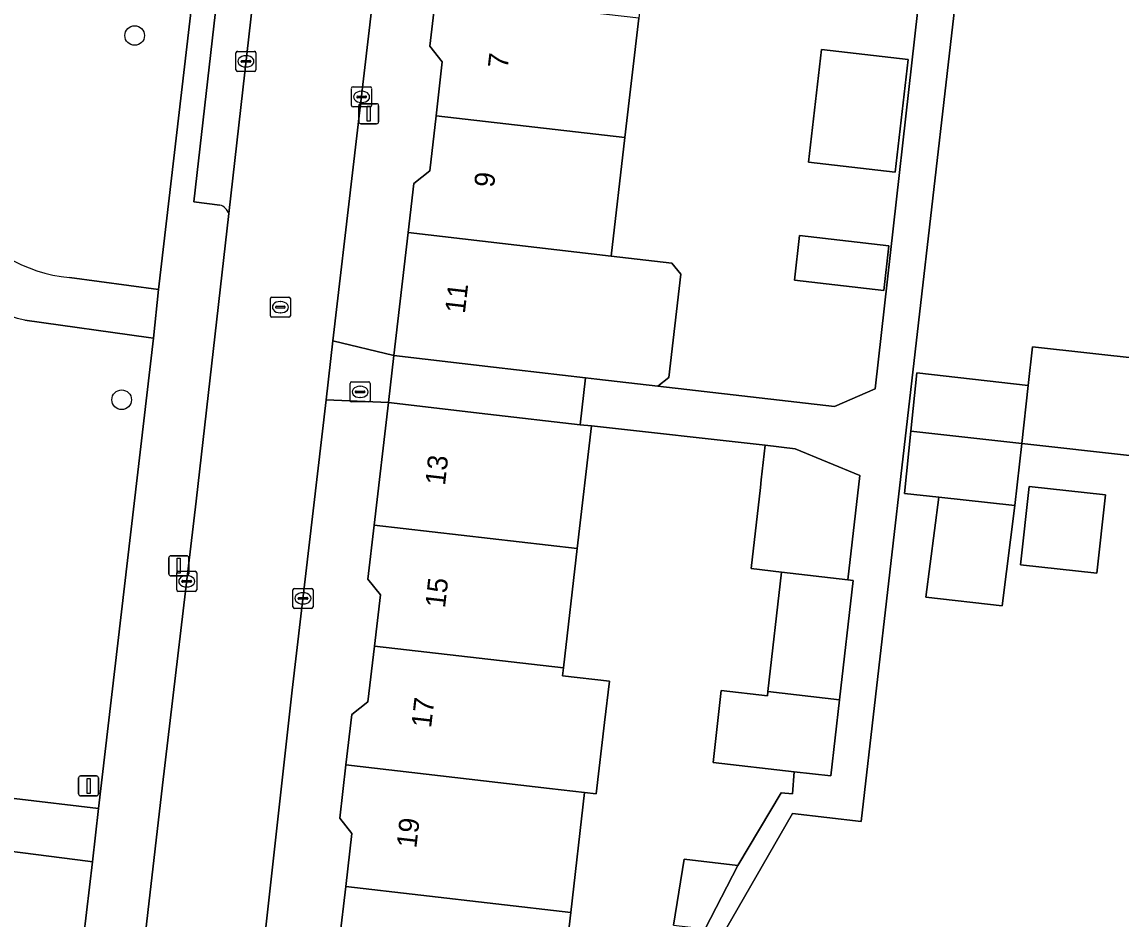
# Model space of a CAD drawing. Extents: x 161692 to 162379, y 380760 to 381678.
# Drawn here: x 162152.4 to 162207.2, y 381154.7 to 381199.4 of the extents above; entities that cross this region are included whole.
import ezdxf

# ---------------------------------------------------------------- set-up
doc = ezdxf.new("R2010")
doc.units = 0
for name, color, linetype in [('IMGEO_Boom', 7, 'Continuous'), ('IMGEO_Brandkraan', 7, 'Continuous'), ('IMGEO_Erf', 7, 'Continuous'), ('IMGEO_Groenvoorziening', 7, 'Continuous'), ('IMGEO_Kolk', 7, 'Continuous'), ('IMGEO_Lichtmast', 7, 'Continuous'), ('IMGEO_Pand', 7, 'Continuous'), ('IMGEO_Pand_nummerreeks', 7, 'Continuous'), ('IMGEO_Pand_overbouw', 7, 'Continuous'), ('IMGEO_Parkeervlak_open', 7, 'Continuous'), ('IMGEO_Rijbaan_lokaal_open', 7, 'Continuous'), ('IMGEO_Rioolput', 7, 'Continuous'), ('IMGEO_Verkeersbordpaal', 7, 'Continuous'), ('IMGEO_Voetpad_gesloten', 7, 'Continuous'), ('IMGEO_Voetpad_open', 7, 'Continuous')]:
    doc.layers.add(name, color=color, linetype=linetype)

msp = doc.modelspace()

# ---------------------------------------------------------------- linework, layer by layer
at = {"layer": 'IMGEO_Boom'}
for centre in [(162157.976, 381198.758), (162157.326, 381180.592)]:
    msp.add_circle(centre, 0.489, dxfattribs=at)
at = {"layer": 'IMGEO_Brandkraan'}
for p, q in [((162168.72, 381180.558), (162168.72, 381181.41)), ((162168.795, 381181.484), (162169.647, 381181.484)), ((162169.208, 381181.264), (162169.233, 381181.264)), ((162169.721, 381181.41), (162169.721, 381180.558)), ((162168.979, 381180.978), (162168.979, 381180.99)), ((162169.417, 381180.941), (162169.019, 381180.941)), ((162169.022, 381181.027), (162169.42, 381181.027)), ((162169.231, 381180.704), (162169.206, 381180.704)), ((162169.463, 381180.99), (162169.463, 381180.978)), ((162169.647, 381180.484), (162168.795, 381180.484))]:
    msp.add_line(p, q, dxfattribs=at)
for points in [[(162168.72, 381180.558), (162168.72, 381181.41)], [(162168.795, 381181.484), (162169.647, 381181.484)], [(162169.721, 381181.41), (162169.721, 381180.558)], [(162169.647, 381180.484), (162168.795, 381180.484)]]:
    msp.add_lwpolyline(points, dxfattribs=at)
for centre, radius, start, end in [((162168.797, 381181.408), 0.0765, 91.552, 178.448), ((162168.797, 381181.408), 0.0765, 91.552, 178.448), ((162169.645, 381181.408), 0.0765, 1.552, 88.448), ((162169.645, 381181.408), 0.0765, 1.552, 88.448), ((162169.019, 381180.987), 0.0403, 85.8775, 175.7526), ((162169.016, 381180.977), 0.0366, 178.938, 274.7102), ((162169.42, 381180.984), 0.043, 264.8664, 352.4533), ((162169.424, 381180.989), 0.0386, 1.7309, 96.639), ((162168.797, 381180.56), 0.0765, 181.552, 268.448), ((162168.797, 381180.56), 0.0765, 181.552, 268.448), ((162169.645, 381180.56), 0.0765, 271.552, 358.448), ((162169.645, 381180.56), 0.0765, 271.552, 358.448)]:
    msp.add_arc(centre, radius, start, end, dxfattribs=at)
for centre, major_axis, ratio, start_param, end_param in [((162169.207, 381180.984), (-0.387, 0.002), 0.722429, 4.712389, 7.853982), ((162169.232, 381180.984), (-0.39, 0.002), 0.717154, 1.570796, 4.712389)]:
    msp.add_ellipse(centre, major_axis=major_axis, ratio=ratio, start_param=start_param, end_param=end_param, dxfattribs=at)
at = {"layer": 'IMGEO_Erf'}
for points in [[(162197.492, 381204.07), (162195.227, 381204.349), (162195.955, 381210.26), (162195.971, 381210.391), (162184.525, 381211.801), (162184.5, 381211.582), (162183.822, 381205.729), (162183.114, 381199.619), (162182.424, 381193.665), (162181.74, 381187.759), (162184.774, 381187.407), (162185.214, 381186.853), (162184.617, 381181.706), (162184.063, 381181.267), (162192.874, 381180.248), (162194.906, 381181.141)], [(162191.586, 381192.438), (162192.238, 381198.066), (162196.558, 381197.565), (162195.906, 381191.937)], [(162190.88, 381186.561), (162191.136, 381188.782), (162195.597, 381188.268), (162195.341, 381186.047)], [(162205.964, 381171.947), (162202.16, 381172.366), (162202.589, 381176.267), (162206.394, 381175.848)]]:
    msp.add_lwpolyline(points, close=True, dxfattribs=at)
for points in [[(162207.712, 381201.997), (162204.798, 381202.356), (162201.896, 381202.774), (162199.213, 381203.105), (162194.213, 381159.563), (162190.787, 381159.956), (162187.187, 381153.72)], [(162207.751, 381177.797), (162202.224, 381178.406), (162201.877, 381175.315), (162201.236, 381170.321), (162197.439, 381170.74), (162198.08, 381175.734), (162196.379, 381175.921), (162196.694, 381179.03), (162196.989, 381181.931), (162202.544, 381181.305), (162202.756, 381183.23), (162208.321, 381182.616)], [(162184.851, 381154.388), (162185.377, 381157.678), (162188.067, 381157.367), (162190.225, 381160.981), (162190.784, 381160.938), (162190.869, 381162.044), (162186.824, 381162.507), (162187.235, 381166.095), (162189.531, 381165.832), (162189.555, 381166.041), (162190.238, 381171.997), (162188.723, 381172.171), (162189.186, 381176.211), (162189.221, 381176.596), (162189.419, 381178.324), (162180.759, 381179.284), (162180.051, 381173.174), (162179.361, 381167.219), (162179.316, 381166.83), (162181.652, 381166.559), (162181.413, 381164.501), (162181.001, 381160.942), (162180.418, 381161.01), (162179.724, 381155.017), (162179.03, 381149.027)]]:
    msp.add_lwpolyline(points, dxfattribs=at)
at = {"layer": 'IMGEO_Groenvoorziening'}
for points in [[(162154.726, 381186.684), (162159.161, 381186.093), (162161.466, 381205.753)], [(162158.923, 381183.669), (162158.67, 381183.704), (162152.495, 381184.57)], [(162135.13, 381162.697), (162156.168, 381160.201), (162158.923, 381183.669)], [(162106.694, 381166.723), (162106.422, 381166.149), (162104.701, 381153.539), (162105.038, 381151.871), (162154.533, 381146.175), (162155.871, 381157.555), (162155.636, 381157.584), (162133.829, 381160.381)]]:
    msp.add_lwpolyline(points, dxfattribs=at)
for centre, radius, start, end in [((162155.544, 381194.539), 7.898, 215.9918, 264.0544), ((162154.454, 381193.294), 8.941, 217.9373, 257.3448)]:
    msp.add_arc(centre, radius, start, end, dxfattribs=at)
at = {"layer": 'IMGEO_Kolk'}
for p, q in [((162163.025, 381197.043), (162163.025, 381197.895)), ((162163.1, 381197.969), (162163.952, 381197.969)), ((162163.513, 381197.749), (162163.538, 381197.749)), ((162164.026, 381197.895), (162164.026, 381197.043)), ((162163.284, 381197.463), (162163.284, 381197.475)), ((162163.722, 381197.426), (162163.324, 381197.426)), ((162163.327, 381197.512), (162163.725, 381197.512)), ((162163.536, 381197.189), (162163.511, 381197.189)), ((162163.768, 381197.475), (162163.768, 381197.463)), ((162163.952, 381196.969), (162163.1, 381196.969)), ((162168.792, 381195.272), (162168.792, 381196.124)), ((162168.867, 381196.198), (162169.719, 381196.198)), ((162169.28, 381195.978), (162169.305, 381195.978)), ((162169.793, 381196.124), (162169.793, 381195.272)), ((162169.051, 381195.692), (162169.051, 381195.704)), ((162169.489, 381195.655), (162169.091, 381195.655)), ((162169.094, 381195.741), (162169.492, 381195.741)), ((162169.303, 381195.418), (162169.278, 381195.418)), ((162169.535, 381195.704), (162169.535, 381195.692)), ((162169.719, 381195.198), (162168.867, 381195.198)), ((162160.071, 381171.111), (162160.071, 381171.963)), ((162160.146, 381172.037), (162160.998, 381172.037)), ((162161.072, 381171.963), (162161.072, 381171.111)), ((162160.33, 381171.531), (162160.33, 381171.543)), ((162160.768, 381171.494), (162160.37, 381171.494)), ((162160.373, 381171.58), (162160.771, 381171.58)), ((162160.559, 381171.817), (162160.584, 381171.817)), ((162160.814, 381171.543), (162160.814, 381171.531)), ((162160.998, 381171.037), (162160.146, 381171.037)), ((162160.582, 381171.257), (162160.557, 381171.257)), ((162165.869, 381170.261), (162165.869, 381171.113)), ((162165.944, 381171.187), (162166.796, 381171.187)), ((162166.171, 381170.73), (162166.569, 381170.73)), ((162166.357, 381170.967), (162166.382, 381170.967)), ((162166.87, 381171.113), (162166.87, 381170.261)), ((162166.796, 381170.187), (162165.944, 381170.187)), ((162166.128, 381170.681), (162166.128, 381170.693)), ((162166.566, 381170.644), (162166.168, 381170.644)), ((162166.38, 381170.407), (162166.355, 381170.407)), ((162166.612, 381170.693), (162166.612, 381170.681))]:
    msp.add_line(p, q, dxfattribs=at)
for points in [[(162163.025, 381197.043), (162163.025, 381197.895)], [(162163.1, 381197.969), (162163.952, 381197.969)], [(162164.026, 381197.895), (162164.026, 381197.043)], [(162163.952, 381196.969), (162163.1, 381196.969)], [(162168.792, 381195.272), (162168.792, 381196.124)], [(162168.867, 381196.198), (162169.719, 381196.198)], [(162169.793, 381196.124), (162169.793, 381195.272)], [(162169.719, 381195.198), (162168.867, 381195.198)], [(162160.071, 381171.111), (162160.071, 381171.963)], [(162160.146, 381172.037), (162160.998, 381172.037)], [(162161.072, 381171.963), (162161.072, 381171.111)], [(162160.998, 381171.037), (162160.146, 381171.037)], [(162165.869, 381170.261), (162165.869, 381171.113)], [(162165.944, 381171.187), (162166.796, 381171.187)], [(162166.87, 381171.113), (162166.87, 381170.261)], [(162166.796, 381170.187), (162165.944, 381170.187)]]:
    msp.add_lwpolyline(points, dxfattribs=at)
for centre, radius, start, end in [((162163.102, 381197.893), 0.0765, 91.552, 178.448), ((162163.102, 381197.893), 0.0765, 91.552, 178.448), ((162163.95, 381197.893), 0.0765, 1.552, 88.448), ((162163.95, 381197.893), 0.0765, 1.552, 88.448), ((162163.102, 381197.045), 0.0765, 181.552, 268.448), ((162163.102, 381197.045), 0.0765, 181.552, 268.448), ((162163.324, 381197.472), 0.0403, 85.8775, 175.7526), ((162163.321, 381197.462), 0.0366, 178.938, 274.7102), ((162163.725, 381197.469), 0.043, 264.8664, 352.4533), ((162163.729, 381197.474), 0.0386, 1.7309, 96.639), ((162163.95, 381197.045), 0.0765, 271.552, 358.448), ((162163.95, 381197.045), 0.0765, 271.552, 358.448), ((162168.869, 381196.122), 0.0765, 91.552, 178.448), ((162168.869, 381196.122), 0.0765, 91.552, 178.448), ((162169.717, 381196.122), 0.0765, 1.552, 88.448), ((162169.717, 381196.122), 0.0765, 1.552, 88.448), ((162169.091, 381195.701), 0.0403, 85.8775, 175.7526), ((162169.088, 381195.691), 0.0366, 178.938, 274.7102), ((162169.492, 381195.698), 0.043, 264.8664, 352.4533), ((162169.496, 381195.703), 0.0386, 1.7309, 96.639), ((162168.869, 381195.274), 0.0765, 181.552, 268.448), ((162168.869, 381195.274), 0.0765, 181.552, 268.448), ((162169.717, 381195.274), 0.0765, 271.552, 358.448), ((162169.717, 381195.274), 0.0765, 271.552, 358.448), ((162160.148, 381171.961), 0.0765, 91.552, 178.448), ((162160.148, 381171.961), 0.0765, 91.552, 178.448), ((162160.996, 381171.961), 0.0765, 1.552, 88.448), ((162160.996, 381171.961), 0.0765, 1.552, 88.448), ((162160.37, 381171.54), 0.0403, 85.8775, 175.7526), ((162160.367, 381171.53), 0.0366, 178.938, 274.7102), ((162160.771, 381171.537), 0.043, 264.8664, 352.4533), ((162160.775, 381171.542), 0.0386, 1.7309, 96.639), ((162160.148, 381171.113), 0.0765, 181.552, 268.448), ((162160.148, 381171.113), 0.0765, 181.552, 268.448), ((162160.996, 381171.113), 0.0765, 271.552, 358.448), ((162160.996, 381171.113), 0.0765, 271.552, 358.448), ((162165.946, 381171.111), 0.0765, 91.552, 178.448), ((162165.946, 381171.111), 0.0765, 91.552, 178.448), ((162166.168, 381170.69), 0.0403, 85.8775, 175.7526), ((162166.573, 381170.692), 0.0386, 1.7309, 96.639), ((162166.794, 381171.111), 0.0765, 1.552, 88.448), ((162166.794, 381171.111), 0.0765, 1.552, 88.448), ((162165.946, 381170.263), 0.0765, 181.552, 268.448), ((162165.946, 381170.263), 0.0765, 181.552, 268.448), ((162166.165, 381170.68), 0.0366, 178.938, 274.7102), ((162166.569, 381170.687), 0.043, 264.8664, 352.4533), ((162166.794, 381170.263), 0.0765, 271.552, 358.448), ((162166.794, 381170.263), 0.0765, 271.552, 358.448)]:
    msp.add_arc(centre, radius, start, end, dxfattribs=at)
for centre, major_axis, ratio, start_param, end_param in [((162163.512, 381197.469), (-0.387, 0.002), 0.722429, 4.712389, 7.853982), ((162163.537, 381197.469), (-0.39, 0.002), 0.717154, 1.570796, 4.712389), ((162169.279, 381195.698), (-0.387, 0.002), 0.722429, 4.712389, 7.853982), ((162169.304, 381195.698), (-0.39, 0.002), 0.717154, 1.570796, 4.712389), ((162160.558, 381171.537), (-0.387, 0.002), 0.722429, 4.712389, 7.853982), ((162160.583, 381171.537), (-0.39, 0.002), 0.717154, 1.570796, 4.712389), ((162166.356, 381170.687), (-0.387, 0.002), 0.722429, 4.712389, 7.853982), ((162166.381, 381170.687), (-0.39, 0.002), 0.717154, 1.570796, 4.712389)]:
    msp.add_ellipse(centre, major_axis=major_axis, ratio=ratio, start_param=start_param, end_param=end_param, dxfattribs=at)
at = {"layer": 'IMGEO_Lichtmast'}
for p, q in [((162169.155, 381194.456), (162169.155, 381195.256)), ((162169.155, 381195.256), (162169.155, 381194.456)), ((162169.255, 381195.356), (162170.045, 381195.356)), ((162170.045, 381195.356), (162169.255, 381195.356)), ((162170.145, 381195.256), (162170.145, 381194.456)), ((162170.145, 381194.456), (162170.145, 381195.256)), ((162170.045, 381194.356), (162169.255, 381194.356)), ((162169.255, 381194.356), (162170.045, 381194.356)), ((162159.679, 381171.911), (162159.679, 381172.711)), ((162159.679, 381172.711), (162159.679, 381171.911)), ((162159.779, 381172.811), (162160.569, 381172.811)), ((162160.569, 381172.811), (162159.779, 381172.811)), ((162160.669, 381172.711), (162160.669, 381171.911)), ((162160.669, 381171.911), (162160.669, 381172.711)), ((162160.569, 381171.811), (162159.779, 381171.811)), ((162159.779, 381171.811), (162160.569, 381171.811))]:
    msp.add_line(p, q, dxfattribs=at)
for points in [[(162169.575, 381195.231), (162169.725, 381195.231), (162169.725, 381194.481), (162169.575, 381194.481), (162169.575, 381195.231)], [(162160.099, 381172.686), (162160.249, 381172.686), (162160.249, 381171.936), (162160.099, 381171.936), (162160.099, 381172.686)]]:
    msp.add_lwpolyline(points, dxfattribs=at)
for centre, start, end in [((162169.255, 381195.256), 90, 180), ((162169.255, 381195.256), 90, 180), ((162170.045, 381195.256), 0, 90), ((162170.045, 381195.256), 360, 90), ((162169.255, 381194.456), 180, 270), ((162169.255, 381194.456), 180, 270), ((162170.045, 381194.456), 270, 0), ((162170.045, 381194.456), 270, 0), ((162159.779, 381172.711), 90, 180), ((162159.779, 381172.711), 90, 180), ((162160.569, 381172.711), 0, 90), ((162160.569, 381172.711), 360, 90), ((162159.779, 381171.911), 180, 270), ((162159.779, 381171.911), 180, 270), ((162160.569, 381171.911), 270, 0), ((162160.569, 381171.911), 270, 0)]:
    msp.add_arc(centre, 0.1, start, end, dxfattribs=at)
at = {"layer": 'IMGEO_Pand'}
for points in [[(162173, 381200.786), (162172.703, 381198.226), (162173.32, 381197.448), (162173.008, 381194.753), (162182.424, 381193.665), (162183.114, 381199.619)], [(162191.586, 381192.438), (162195.906, 381191.937), (162196.558, 381197.565), (162192.238, 381198.066)], [(162171.61, 381188.928), (162181.74, 381187.759), (162182.424, 381193.665), (162173.008, 381194.753), (162172.69, 381192.008), (162171.894, 381191.377)], [(162171.61, 381188.928), (162170.9, 381182.792), (162175.867, 381182.216), (162180.461, 381181.684), (162181.029, 381181.618), (162184.063, 381181.267), (162184.617, 381181.706), (162185.214, 381186.853), (162184.774, 381187.407), (162181.74, 381187.759)], [(162190.88, 381186.561), (162195.341, 381186.047), (162195.597, 381188.268), (162191.136, 381188.782)], [(162208.321, 381182.616), (162202.756, 381183.23), (162202.544, 381181.305), (162202.224, 381178.406), (162207.751, 381177.797), (162207.852, 381178.768), (162207.866, 381178.766), (162207.957, 381179.536)], [(162202.544, 381181.305), (162196.989, 381181.931), (162196.694, 381179.03), (162202.224, 381178.406)], [(162169.921, 381174.343), (162180.051, 381173.174), (162180.759, 381179.284), (162180.19, 381179.35), (162175.597, 381179.882), (162170.63, 381180.457)], [(162202.224, 381178.406), (162196.694, 381179.03), (162196.379, 381175.921), (162198.08, 381175.734), (162201.877, 381175.315)], [(162189.419, 381178.324), (162189.221, 381176.596), (162189.186, 381176.211), (162188.723, 381172.171), (162190.238, 381171.997), (162193.552, 381171.616), (162194.148, 381176.823), (162190.916, 381178.14)], [(162202.16, 381172.366), (162205.964, 381171.947), (162206.394, 381175.848), (162202.589, 381176.267)], [(162201.877, 381175.315), (162198.08, 381175.734), (162197.439, 381170.74), (162201.236, 381170.321)], [(162169.921, 381174.343), (162169.609, 381171.649), (162170.229, 381170.866), (162169.933, 381168.308), (162179.361, 381167.219), (162180.051, 381173.174)], [(162193.819, 381171.585), (162193.552, 381171.616), (162190.238, 381171.997), (162189.555, 381166.041), (162193.137, 381165.628)], [(162179.361, 381167.219), (162169.933, 381168.308), (162169.611, 381165.531), (162168.804, 381164.892), (162168.514, 381162.385), (162178.666, 381161.213), (162180.418, 381161.01), (162181.001, 381160.942), (162181.413, 381164.501), (162181.652, 381166.559), (162179.316, 381166.83)], [(162193.137, 381165.628), (162189.555, 381166.041), (162189.531, 381165.832), (162187.235, 381166.095), (162186.824, 381162.507), (162190.869, 381162.044), (162192.702, 381161.834)], [(162168.514, 381162.385), (162168.206, 381159.728), (162168.809, 381158.967), (162168.502, 381156.312), (162179.724, 381155.017), (162180.418, 381161.01), (162178.666, 381161.213)], [(162188.067, 381157.367), (162185.377, 381157.678), (162184.851, 381154.388), (162186.438, 381154.204)], [(162167.107, 381150.404), (162177.278, 381149.23), (162179.03, 381149.027), (162179.724, 381155.017), (162168.502, 381156.312), (162168.194, 381153.652), (162167.412, 381153.033)]]:
    msp.add_lwpolyline(points, close=True, dxfattribs=at)
at = {"layer": 'IMGEO_Pand_overbouw'}
msp.add_lwpolyline([(162180.461, 381181.684), (162175.867, 381182.216), (162170.9, 381182.792), (162170.63, 381180.457), (162175.597, 381179.882), (162180.19, 381179.35)], close=True, dxfattribs=at)
at = {"layer": 'IMGEO_Parkeervlak_open'}
for points in [[(162165.379, 381217.776), (162164.081, 381217.922), (162163.47, 381212.732), (162163.309, 381211.36), (162160.922, 381190.465), (162162.23, 381190.304)], [(162162.665, 381189.882), (162164.169, 381203.109), (162165.907, 381218.2)]]:
    msp.add_lwpolyline(points, dxfattribs=at)
msp.add_arc((162162.022, 381189.655), 0.682, 19.4701, 72.268, dxfattribs=at)
at = {"layer": 'IMGEO_Rijbaan_lokaal_open'}
msp.add_lwpolyline([(162169.829, 381200.284), (162171.071, 381211.199), (162171.924, 381218.412), (162166.013, 381219.121), (162165.907, 381218.2), (162164.169, 381203.109), (162162.665, 381189.882), (162161.049, 381175.536), (162159.365, 381161.363), (162157.908, 381148.676), (162157.877, 381148.391), (162163.756, 381147.701), (162163.848, 381148.312), (162165.836, 381166.11), (162167.521, 381180.59), (162167.867, 381183.539)], close=True, dxfattribs=at)
at = {"layer": 'IMGEO_Rioolput'}
for p, q in [((162164.742, 381184.784), (162164.742, 381185.636)), ((162164.817, 381185.71), (162165.669, 381185.71)), ((162165.743, 381185.636), (162165.743, 381184.784)), ((162165.001, 381185.204), (162165.001, 381185.216)), ((162165.439, 381185.167), (162165.041, 381185.167)), ((162165.044, 381185.253), (162165.442, 381185.253)), ((162165.23, 381185.49), (162165.255, 381185.49)), ((162165.485, 381185.216), (162165.485, 381185.204)), ((162165.669, 381184.71), (162164.817, 381184.71)), ((162165.253, 381184.93), (162165.228, 381184.93))]:
    msp.add_line(p, q, dxfattribs=at)
for points in [[(162164.742, 381184.784), (162164.742, 381185.636)], [(162164.817, 381185.71), (162165.669, 381185.71)], [(162165.743, 381185.636), (162165.743, 381184.784)], [(162165.669, 381184.71), (162164.817, 381184.71)]]:
    msp.add_lwpolyline(points, dxfattribs=at)
for centre, radius, start, end in [((162164.819, 381185.634), 0.0765, 91.552, 178.448), ((162164.819, 381185.634), 0.0765, 91.552, 178.448), ((162165.667, 381185.634), 0.0765, 1.552, 88.448), ((162165.667, 381185.634), 0.0765, 1.552, 88.448), ((162165.041, 381185.213), 0.0403, 85.8775, 175.7526), ((162165.038, 381185.203), 0.0366, 178.938, 274.7102), ((162165.442, 381185.21), 0.043, 264.8664, 352.4533), ((162165.446, 381185.215), 0.0386, 1.7309, 96.639), ((162164.819, 381184.786), 0.0765, 181.552, 268.448), ((162164.819, 381184.786), 0.0765, 181.552, 268.448), ((162165.667, 381184.786), 0.0765, 271.552, 358.448), ((162165.667, 381184.786), 0.0765, 271.552, 358.448)]:
    msp.add_arc(centre, radius, start, end, dxfattribs=at)
for centre, major_axis, ratio, start_param, end_param in [((162165.229, 381185.21), (-0.387, 0.002), 0.722429, 4.712389, 7.853982), ((162165.254, 381185.21), (-0.39, 0.002), 0.717154, 1.570796, 4.712389)]:
    msp.add_ellipse(centre, major_axis=major_axis, ratio=ratio, start_param=start_param, end_param=end_param, dxfattribs=at)
at = {"layer": 'IMGEO_Verkeersbordpaal'}
for p, q in [((162155.18, 381160.935), (162155.18, 381161.735)), ((162155.18, 381161.735), (162155.18, 381160.935)), ((162155.28, 381161.835), (162156.07, 381161.835)), ((162156.07, 381161.835), (162155.28, 381161.835)), ((162156.17, 381161.735), (162156.17, 381160.935)), ((162156.17, 381160.935), (162156.17, 381161.735)), ((162156.07, 381160.835), (162155.28, 381160.835)), ((162155.28, 381160.835), (162156.07, 381160.835))]:
    msp.add_line(p, q, dxfattribs=at)
msp.add_lwpolyline([(162155.6, 381161.71), (162155.75, 381161.71), (162155.75, 381160.96), (162155.6, 381160.96), (162155.6, 381161.71)], dxfattribs=at)
for centre, start, end in [((162155.28, 381161.735), 90, 180), ((162155.28, 381161.735), 90, 180), ((162156.07, 381161.735), 0, 90), ((162156.07, 381161.735), 360, 90), ((162155.28, 381160.935), 180, 270), ((162155.28, 381160.935), 180, 270), ((162156.07, 381160.935), 270, 0), ((162156.07, 381160.935), 270, 0)]:
    msp.add_arc(centre, 0.1, start, end, dxfattribs=at)
at = {"layer": 'IMGEO_Voetpad_gesloten'}
for points in [[(162152.495, 381184.57), (162158.67, 381183.704), (162158.923, 381183.669), (162159.161, 381186.093), (162154.726, 381186.684)], [(162133.829, 381160.381), (162155.636, 381157.584), (162155.871, 381157.555), (162156.168, 381160.201), (162135.13, 381162.697)]]:
    msp.add_lwpolyline(points, dxfattribs=at)
for centre, radius, start, end in [((162155.544, 381194.539), 7.898, 215.9918, 264.0544), ((162154.454, 381193.294), 8.941, 217.9373, 257.3448)]:
    msp.add_arc(centre, radius, start, end, dxfattribs=at)
at = {"layer": 'IMGEO_Voetpad_open'}
for points in [[(162175.215, 381220.135), (162172.048, 381219.464), (162171.924, 381218.412), (162171.071, 381211.199), (162169.829, 381200.284), (162167.867, 381183.539), (162170.9, 381182.792), (162171.61, 381188.928), (162171.894, 381191.377), (162172.69, 381192.008), (162173.008, 381194.753), (162173.32, 381197.448), (162172.703, 381198.226), (162173, 381200.786), (162173.292, 381203.31), (162174.112, 381203.96), (162174.442, 381206.811), (162174.723, 381209.233), (162174.05, 381210.083), (162174.359, 381212.753)], [(162170.9, 381182.792), (162167.867, 381183.539), (162167.521, 381180.59), (162170.63, 381180.457)], [(162170.63, 381180.457), (162175.597, 381179.882), (162180.19, 381179.35), (162180.461, 381181.684), (162175.867, 381182.216), (162170.9, 381182.792)]]:
    msp.add_lwpolyline(points, close=True, dxfattribs=at)
for points in [[(162165.907, 381218.2), (162162.968, 381218.562), (162161.466, 381205.753), (162159.161, 381186.093), (162158.923, 381183.669), (162156.168, 381160.201), (162155.871, 381157.555), (162154.533, 381146.175), (162157.097, 381145.971)], [(162162.23, 381190.304), (162160.922, 381190.465), (162163.309, 381211.36), (162163.47, 381212.732), (162164.081, 381217.922), (162165.379, 381217.776)], [(162197.492, 381204.07), (162194.906, 381181.141), (162192.874, 381180.248), (162184.063, 381181.267), (162181.029, 381181.618), (162180.461, 381181.684), (162180.19, 381179.35), (162180.759, 381179.284), (162189.419, 381178.324), (162190.916, 381178.14), (162194.148, 381176.823), (162193.552, 381171.616), (162193.819, 381171.585), (162193.137, 381165.628), (162192.702, 381161.834), (162190.869, 381162.044), (162190.784, 381160.938), (162190.225, 381160.981), (162188.067, 381157.367), (162186.438, 381154.204)], [(162187.187, 381153.72), (162190.787, 381159.956), (162194.213, 381159.563), (162199.213, 381203.105)], [(162161.049, 381175.536), (162162.665, 381189.882)], [(162168.194, 381153.652), (162168.502, 381156.312), (162168.809, 381158.967), (162168.206, 381159.728), (162168.514, 381162.385), (162168.804, 381164.892), (162169.611, 381165.531), (162169.933, 381168.308), (162170.229, 381170.866), (162169.609, 381171.649), (162169.921, 381174.343), (162170.63, 381180.457), (162167.521, 381180.59), (162165.836, 381166.11), (162163.848, 381148.312)], [(162157.811, 381148.076), (162157.877, 381148.391), (162157.908, 381148.676), (162159.365, 381161.363), (162161.049, 381175.536)]]:
    msp.add_lwpolyline(points, dxfattribs=at)
msp.add_arc((162162.022, 381189.655), 0.682, 19.4701, 72.268, dxfattribs=at)

# ---------------------------------------------------------------- texts
at = {"layer": 'IMGEO_Pand_nummerreeks'}
for s, rotation, p in [('7', 83.3941, (162176.579, 381197.078)), ('9', 83.3941, (162175.893, 381191.148)), ('11', 83.3955, (162174.442, 381184.865)), ('13', 83.4038, (162173.45, 381176.293)), ('15', 83.3924, (162173.451, 381170.177)), ('17', 83.394, (162172.759, 381164.197)), ('19', 83.3996, (162172.022, 381158.202))]:
    msp.add_text(s, height=1, rotation=rotation, dxfattribs=at).set_placement(p)

doc.saveas('drawing.dxf')
